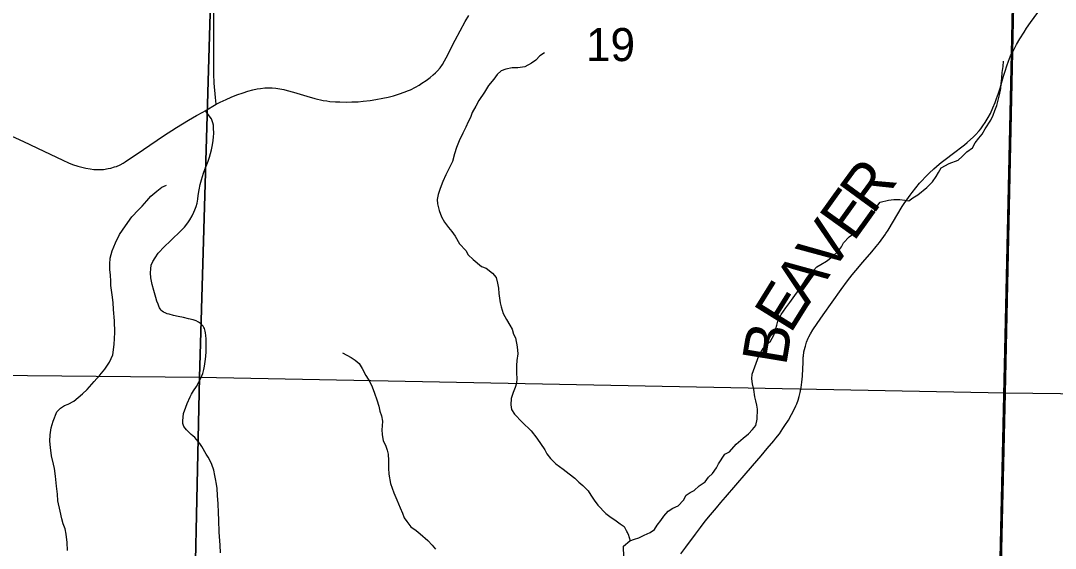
# Model space of a CAD drawing. Extents: x 0 to 34, y 0 to 22.
# Drawn here: x 5.283 to 6.594, y 14.696 to 15.364 of the extents above; entities that cross this region are included whole.
import ezdxf

# ---------------------------------------------------------------- set-up
doc = ezdxf.new("R2010")
doc.units = 0
for name, color, linetype in [('GM_X_Corporation', 7, 'Continuous'), ('GM_X_County_Road_Text', 7, 'Continuous'), ('GM_X_Interchange_Ramps', 7, 'Continuous'), ('GM_X_Interstate_Route', 7, 'Continuous'), ('GM_X_Major_Lake', 7, 'Continuous'), ('GM_X_Minor_Lake', 7, 'Continuous'), ('GM_X_Township_Road_Text', 7, 'Continuous'), ('GM_X_Unincorporated_Text', 7, 'Continuous')]:
    doc.layers.add(name, color=color, linetype=linetype)

msp = doc.modelspace()

# ---------------------------------------------------------------- linework, layer by layer
at = {"layer": 'GM_X_Corporation'}
msp.add_line((5.5168, 15.2503), (5.5307, 15.2585), dxfattribs=at)
for points in [[(6.5452, 15.3343), (6.5495, 15.3413), (6.5548, 15.3499), (6.5578, 15.3549), (6.563, 15.3623), (6.5675, 15.3683), (6.5735, 15.3765), (6.5781, 15.3825), (6.583, 15.3891), (6.5864, 15.3936), (6.5904, 15.3992), (6.594, 15.404), (6.5973, 15.4086), (6.6007, 15.4135), (6.6049, 15.4191), (6.6077, 15.4229)], [(5.5307, 15.2585), (5.5358, 15.261), (5.5433, 15.2647), (5.5499, 15.2676), (5.557, 15.2704), (5.565, 15.2731), (5.571, 15.275), (5.5775, 15.2768), (5.5828, 15.278), (5.5872, 15.2787), (5.5926, 15.2793), (5.5964, 15.2794), (5.6016, 15.2793), (5.6066, 15.2788), (5.6115, 15.2781), (5.6167, 15.2771), (5.6206, 15.2761), (5.6288, 15.2738), (5.6456, 15.2688), (5.656, 15.2658), (5.6592, 15.265), (5.6629, 15.2642), (5.6666, 15.2633), (5.6711, 15.2627), (5.6748, 15.2622), (5.6822, 15.2615), (5.6877, 15.2614), (5.6964, 15.2613), (5.7028, 15.2614), (5.7106, 15.2618), (5.7173, 15.2623), (5.7261, 15.2634), (5.7334, 15.2645), (5.7421, 15.2661), (5.749, 15.2677), (5.7556, 15.2694), (5.7631, 15.2718), (5.7692, 15.2738), (5.7744, 15.2759), (5.777, 15.277), (5.7833, 15.2802), (5.7881, 15.2829), (5.7916, 15.2851), (5.7969, 15.2886), (5.8019, 15.2924), (5.8059, 15.2956), (5.8087, 15.2982), (5.8112, 15.301), (5.8148, 15.3048), (5.8177, 15.309), (5.8204, 15.3134), (5.8225, 15.3175), (5.8339, 15.3397), (5.84, 15.3517), (5.8464, 15.3632), (5.8509, 15.3708)], [(6.3797, 15.0948), (6.3824, 15.0992), (6.4005, 15.129), (6.403, 15.1328), (6.4106, 15.1435), (6.4132, 15.1469), (6.4225, 15.1584), (6.4252, 15.1615), (6.4299, 15.1664), (6.4346, 15.1711), (6.4404, 15.1766), (6.4473, 15.1827), (6.4498, 15.1847), (6.4564, 15.1898), (6.4638, 15.1955), (6.4795, 15.2072), (6.4829, 15.2099), (6.4908, 15.2171), (6.4933, 15.2197), (6.4979, 15.2249), (6.4999, 15.2274), (6.5026, 15.2311), (6.5055, 15.2353), (6.507, 15.2376), (6.5093, 15.2416), (6.5121, 15.2469), (6.5154, 15.2538), (6.5183, 15.2607), (6.5201, 15.2657), (6.5224, 15.2725), (6.5244, 15.2791), (6.527, 15.2881), (6.5288, 15.2941), (6.5308, 15.3005), (6.533, 15.3072), (6.5351, 15.3132), (6.5364, 15.3167), (6.5378, 15.3199), (6.5404, 15.3251), (6.5431, 15.3302), (6.5452, 15.3343)], [(5.2662, 15.2207), (5.2868, 15.2112), (5.3123, 15.1992), (5.3364, 15.1876), (5.3437, 15.1843), (5.3487, 15.1824), (5.3555, 15.1802), (5.3606, 15.1787), (5.3658, 15.1776), (5.371, 15.1766), (5.3759, 15.1761), (5.3802, 15.1759), (5.388, 15.1761), (5.3941, 15.177), (5.3973, 15.1777), (5.4021, 15.1791), (5.4044, 15.1799), (5.4091, 15.182), (5.4128, 15.184), (5.4153, 15.1855), (5.4385, 15.2012), (5.4639, 15.2185), (5.4806, 15.2293), (5.4957, 15.2384), (5.5058, 15.2444), (5.5138, 15.2487), (5.5168, 15.2503)], [(6.1199, 14.689), (6.126, 14.6974), (6.1382, 14.714), (6.1447, 14.7226), (6.1508, 14.7304), (6.1575, 14.7386), (6.165, 14.7473), (6.1706, 14.7539), (6.1765, 14.7609), (6.2025, 14.7911), (6.2162, 14.8069), (6.2216, 14.8132), (6.2293, 14.8224), (6.2377, 14.8323), (6.2402, 14.8355), (6.2447, 14.8412), (6.249, 14.8476), (6.2518, 14.8517), (6.2561, 14.8584), (6.2602, 14.8655), (6.2626, 14.8701), (6.2657, 14.8767), (6.2668, 14.8792), (6.2685, 14.8837), (6.2698, 14.8882), (6.2711, 14.8936), (6.2722, 14.8996), (6.2733, 14.9067), (6.2739, 14.9143), (6.2744, 14.9239), (6.2747, 14.9309), (6.275, 14.9383), (6.2752, 14.9396), (6.2758, 14.9448), (6.2772, 14.9509), (6.2776, 14.9523), (6.2792, 14.957), (6.2813, 14.9621), (6.2821, 14.964), (6.2841, 14.9677), (6.2872, 14.9726), (6.2927, 14.9809), (6.3, 14.9916), (6.3232, 15.0239), (6.3312, 15.0349), (6.3369, 15.0425), (6.3415, 15.0481), (6.3504, 15.0585), (6.3618, 15.0715), (6.3675, 15.0783), (6.3714, 15.0835), (6.3791, 15.0939), (6.3797, 15.0948)]]:
    msp.add_lwpolyline(points, dxfattribs=at)
at = {"layer": 'GM_X_Interchange_Ramps'}
msp.add_lwpolyline([(2.1, 17.9098), (2.1, 14.1), (6.5113, 14.1), (6.5389, 15.3228), (6.5411, 15.4243), (6.5572, 16.1864), (6.5647, 16.5359), (6.5883, 17.471), (6.5943, 17.9356)], dxfattribs=at)
msp.add_lwpolyline([(6.5113, 14.1), (8.9, 14.1), (8.9, 17.8921), (8.5492, 17.9006), (8.3297, 17.9059), (7.6027, 17.9156), (6.5943, 17.9356), (6.5883, 17.471), (6.5647, 16.5359), (6.5572, 16.1864), (6.5411, 15.4243), (6.5389, 15.3228)], close=True, dxfattribs=at)
at = {"layer": 'GM_X_Interstate_Route'}
msp.add_line((5.5168, 15.2503), (5.5307, 15.2585), dxfattribs=at)
for points in [[(5.5307, 15.2585), (5.5299, 15.2669), (5.5283, 15.2851), (5.5281, 15.2886), (5.528, 15.2935), (5.5278, 15.3828)], [(5.5365, 14.6904), (5.5357, 14.6999), (5.5348, 14.7166), (5.5342, 14.7318), (5.5338, 14.7415), (5.5334, 14.7522), (5.5327, 14.7629), (5.532, 14.772), (5.5313, 14.7775), (5.5301, 14.7839), (5.5292, 14.7884), (5.5277, 14.7949), (5.5253, 14.8021), (5.5231, 14.8069), (5.5206, 14.8115), (5.5183, 14.8154), (5.5126, 14.8248), (5.5099, 14.8288), (5.5058, 14.8338), (5.5036, 14.8363), (5.5014, 14.8384), (5.499, 14.8404), (5.4964, 14.8427), (5.4931, 14.846), (5.4899, 14.8504), (5.4887, 14.854), (5.4884, 14.8576), (5.4894, 14.8667), (5.4922, 14.875), (5.494, 14.8793), (5.4977, 14.8878), (5.4995, 14.8912), (5.5021, 14.8957), (5.5057, 14.901), (5.5092, 14.9072), (5.5111, 14.9109), (5.5127, 14.9144), (5.5138, 14.9176), (5.5152, 14.9224), (5.516, 14.9268), (5.5169, 14.9325), (5.5177, 14.9391), (5.518, 14.9455), (5.5181, 14.9565), (5.518, 14.9613), (5.5177, 14.9655), (5.5172, 14.9692), (5.5169, 14.9713), (5.5165, 14.9729), (5.516, 14.9745), (5.5152, 14.9759), (5.5142, 14.9775), (5.5131, 14.9788), (5.5108, 14.9809), (5.5083, 14.9825), (5.5054, 14.984), (5.5017, 14.9853), (5.4958, 14.9869), (5.4895, 14.9883), (5.4828, 14.9897), (5.4767, 14.9911), (5.4713, 14.9925), (5.4685, 14.9932), (5.466, 14.9942), (5.464, 14.9953), (5.4625, 14.9966), (5.4612, 14.9977), (5.46, 14.9994), (5.4591, 15.0008), (5.4582, 15.0027), (5.4573, 15.0051), (5.4558, 15.0093), (5.4544, 15.0137), (5.4517, 15.0226), (5.4498, 15.0302), (5.4482, 15.0385), (5.4475, 15.0448), (5.4478, 15.0502), (5.4486, 15.0545), (5.4505, 15.0592), (5.4535, 15.0642), (5.4575, 15.0699), (5.4652, 15.0783), (5.4727, 15.0853), (5.4873, 15.0994), (5.4905, 15.1029), (5.4949, 15.1084), (5.4974, 15.1123), (5.5002, 15.117), (5.5027, 15.122), (5.5039, 15.1248), (5.5055, 15.129), (5.5067, 15.1331), (5.5077, 15.1384), (5.5082, 15.143), (5.5093, 15.1503), (5.5106, 15.1569), (5.5121, 15.1628), (5.5133, 15.167), (5.5147, 15.1714), (5.5166, 15.176), (5.5205, 15.1864), (5.5223, 15.1914), (5.5238, 15.196), (5.5251, 15.2009), (5.5263, 15.2071), (5.527, 15.2125), (5.5275, 15.2172), (5.5277, 15.2217), (5.5276, 15.2286), (5.5273, 15.232), (5.5267, 15.235), (5.5259, 15.2376), (5.5248, 15.24), (5.5233, 15.2423), (5.5198, 15.2467), (5.518, 15.2489), (5.5168, 15.2503)]]:
    msp.add_lwpolyline(points, dxfattribs=at)
at = {"layer": 'GM_X_Minor_Lake'}
for points in [[(5.5393, 15.9226), (5.5097, 14.9125), (4.5059, 14.9222), (4.5275, 15.9394)], [(6.553, 15.9139), (6.5307, 14.8925), (5.5097, 14.9125), (5.5393, 15.9226)], [(7.5725, 15.8874), (7.5466, 14.8803), (6.5307, 14.8925), (6.553, 15.9139)]]:
    msp.add_lwpolyline(points, close=True, dxfattribs=at)
at = {"layer": 'GM_X_Township_Road_Text'}
for points in [[(5.9468, 15.3235), (5.9412, 15.32), (5.936, 15.3146), (5.9307, 15.3107), (5.9221, 15.306), (5.913, 15.3048), (5.9062, 15.3047), (5.8979, 15.303), (5.8919, 15.301), (5.887, 15.2964), (5.8826, 15.2902), (5.8759, 15.2821), (5.8711, 15.2737), (5.8637, 15.2633), (5.86, 15.256), (5.8552, 15.2479), (5.853, 15.2418), (5.8501, 15.2364), (5.8471, 15.2296), (5.8435, 15.2219), (5.839, 15.2123), (5.8354, 15.2039), (5.8329, 15.1958), (5.8303, 15.1859), (5.8252, 15.1759), (5.8219, 15.169), (5.8182, 15.1606), (5.8146, 15.1518), (5.812, 15.1441), (5.811, 15.138), (5.8114, 15.1323), (5.8135, 15.124), (5.8166, 15.116), (5.8201, 15.1092), (5.8255, 15.1025), (5.8297, 15.0972), (5.8336, 15.0916), (5.8394, 15.0818), (5.8471, 15.0731), (5.8502, 15.0678), (5.8564, 15.0618), (5.8671, 15.0532), (5.8732, 15.051), (5.8809, 15.0447), (5.8859, 15.0391), (5.8875, 15.0318), (5.8887, 15.0254), (5.8892, 15.0189), (5.8909, 15.0068), (5.8921, 15.0018), (5.8945, 14.9935), (5.8988, 14.986), (5.903, 14.9788), (5.9058, 14.9735), (5.9077, 14.9674), (5.9101, 14.9625), (5.9125, 14.9512), (5.913, 14.9424), (5.912, 14.934), (5.9113, 14.9275), (5.9115, 14.918), (5.912, 14.9112), (5.9117, 14.9051), (5.9099, 14.8997), (5.9073, 14.8932), (5.9048, 14.886), (5.9041, 14.8776), (5.905, 14.8719), (5.9088, 14.8658), (5.9188, 14.8557), (5.93, 14.8448), (5.9373, 14.8354), (5.9474, 14.8207), (5.9501, 14.8158), (5.9547, 14.8098), (5.9612, 14.8031), (5.9708, 14.7964), (5.9781, 14.7904), (5.9854, 14.7848), (5.9904, 14.7799), (5.9957, 14.7758), (6.0023, 14.7687), (6.0057, 14.7634), (6.01, 14.757), (6.0146, 14.7506), (6.0246, 14.7401), (6.0296, 14.7364), (6.038, 14.7308), (6.043, 14.727), (6.048, 14.7237), (6.0507, 14.7188), (6.053, 14.7139), (6.0556, 14.7057)], [(6.2135, 14.926), (6.2186, 14.9398), (6.223, 14.9475), (6.2279, 14.954), (6.2335, 14.9583), (6.2375, 14.966), (6.2415, 14.9786), (6.2429, 14.9839), (6.247, 14.9924), (6.2529, 15.0005), (6.2581, 15.0074), (6.2641, 15.0162), (6.27, 15.0243), (6.2748, 15.0309), (6.2785, 15.037), (6.2826, 15.0424), (6.2878, 15.0478), (6.2923, 15.0528), (6.2972, 15.0556), (6.3043, 15.0599), (6.3118, 15.0653), (6.3196, 15.073), (6.3234, 15.078), (6.3259, 15.083), (6.333, 15.0904), (6.3386, 15.0946), (6.3435, 15.0985), (6.3499, 15.1032), (6.3558, 15.1105), (6.3618, 15.1167), (6.3647, 15.1224), (6.3684, 15.129), (6.3725, 15.1344), (6.3831, 15.1372), (6.3899, 15.1377), (6.3974, 15.1378), (6.4039, 15.1371), (6.4088, 15.1361), (6.4137, 15.1399), (6.4201, 15.1438), (6.4317, 15.1532), (6.4388, 15.1601), (6.4436, 15.167), (6.4462, 15.172), (6.4499, 15.1782), (6.46, 15.1833), (6.4713, 15.1876), (6.4765, 15.1923), (6.4825, 15.1981), (6.4893, 15.2035), (6.4929, 15.2097), (6.4974, 15.2154), (6.5019, 15.2208), (6.5056, 15.2274), (6.5126, 15.2385), (6.5155, 15.2446), (6.5177, 15.2508), (6.5203, 15.2569), (6.5235, 15.2706), (6.5253, 15.2787), (6.5259, 15.2848), (6.5266, 15.2916), (6.5272, 15.2989), (6.5283, 15.3065), (6.5289, 15.313)], [(5.4021, 14.9843), (5.4007, 14.9987), (5.4002, 15.0075), (5.3989, 15.0173), (5.3973, 15.0291), (5.3972, 15.0344), (5.3967, 15.042), (5.3962, 15.0493), (5.3961, 15.0561), (5.3964, 15.0634), (5.3989, 15.0729), (5.4033, 15.0832), (5.4084, 15.0936), (5.4158, 15.1047), (5.424, 15.1159), (5.4322, 15.1248), (5.4371, 15.1294), (5.443, 15.1364), (5.4478, 15.1421), (5.4557, 15.1483), (5.4621, 15.1534), (5.4677, 15.1561)], [(5.3423, 14.6934), (5.3418, 14.7036), (5.3405, 14.7139), (5.3393, 14.7207), (5.3369, 14.7271), (5.3353, 14.7332), (5.3329, 14.7431), (5.3301, 14.756), (5.3296, 14.7647), (5.3286, 14.7746), (5.3273, 14.7875), (5.3257, 14.797), (5.3245, 14.8027), (5.322, 14.8133), (5.3207, 14.8236), (5.3199, 14.8319), (5.3205, 14.8396), (5.3215, 14.8487), (5.324, 14.8571), (5.3288, 14.869), (5.3336, 14.8736), (5.3385, 14.8768), (5.3434, 14.8787), (5.3502, 14.8826), (5.3614, 14.8916), (5.3674, 14.897), (5.3763, 14.9074), (5.3834, 14.9155), (5.3897, 14.9228), (5.3956, 14.932), (5.3997, 14.9412), (5.4017, 14.9542), (5.4023, 14.9694), (5.4021, 14.9843)], [(5.6908, 14.9436), (5.7018, 14.9377), (5.7072, 14.9344), (5.7122, 14.9303), (5.716, 14.9238), (5.7207, 14.9148), (5.7258, 14.9069), (5.7285, 14.9004), (5.7316, 14.8925), (5.7344, 14.8842), (5.7368, 14.8762), (5.7384, 14.8697), (5.7404, 14.8637), (5.7416, 14.8569), (5.7413, 14.8511), (5.741, 14.8462), (5.7411, 14.8401), (5.7424, 14.8321), (5.7455, 14.8268), (5.7475, 14.8204), (5.7487, 14.8151), (5.7492, 14.8071), (5.7493, 14.7976), (5.7498, 14.79), (5.7519, 14.7782), (5.7558, 14.7665), (5.7597, 14.7574), (5.7641, 14.7472), (5.7668, 14.7404), (5.7692, 14.7347), (5.7726, 14.7298), (5.7777, 14.7234), (5.7845, 14.7186), (5.7895, 14.7145), (5.7991, 14.7059), (5.8045, 14.7002), (5.8087, 14.695)], [(6.0474, 14.6849), (6.0472, 14.6989), (6.0551, 14.7055), (6.0611, 14.7075), (6.0664, 14.7095), (6.0735, 14.7127), (6.081, 14.7162), (6.0863, 14.7197), (6.09, 14.7255), (6.0944, 14.7312), (6.0981, 14.7366), (6.1037, 14.7432), (6.1097, 14.7471), (6.1165, 14.7498), (6.1232, 14.7572), (6.1265, 14.7633), (6.1318, 14.7668), (6.1367, 14.7692), (6.143, 14.775), (6.1505, 14.7801), (6.155, 14.7862), (6.1598, 14.7909), (6.165, 14.7978), (6.1676, 14.8032), (6.1757, 14.8151), (6.1814, 14.8182), (6.1899, 14.8278), (6.1989, 14.8356), (6.2057, 14.841), (6.2105, 14.8464), (6.215, 14.8514), (6.2167, 14.8598), (6.2169, 14.8724), (6.2161, 14.8773), (6.2149, 14.883), (6.2137, 14.888), (6.2124, 14.8971), (6.2108, 14.9043), (6.2099, 14.9107), (6.2102, 14.9168), (6.2135, 14.926)], [(6.0512, 14.7163), (6.0511, 14.7165)]]:
    msp.add_lwpolyline(points, dxfattribs=at)
at = {"layer": 'GM_X_Unincorporated_Text'}
for points in [[(4.484, 14.1), (5.492, 14.1), (5.5097, 14.9125), (4.5059, 14.9222)], [(5.492, 14.1), (6.5122, 14.1), (6.5307, 14.8925), (5.5097, 14.9125)], [(6.5122, 14.1), (7.5285, 14.1), (7.5466, 14.8803), (6.5307, 14.8925)]]:
    msp.add_lwpolyline(points, close=True, dxfattribs=at)

# ---------------------------------------------------------------- texts
at = {"layer": 'GM_X_County_Road_Text'}
msp.add_text('19', height=0.04186, rotation=0, dxfattribs=at).set_placement((5.9995, 15.3132))
at = {"layer": 'GM_X_Major_Lake'}
for s, rotation, p in [('R', 53.8108, (6.3635, 15.1176)), ('E', 54.3353, (6.3388, 15.0832)), ('V', 54.3374, (6.3097, 15.0426)), ('A', 54.395, (6.2806, 15.002)), ('E', 58.1182, (6.2587, 14.9667)), ('B', 80.6814, (6.2532, 14.9261))]:
    msp.add_text(s, height=0.0568, rotation=rotation, dxfattribs=at).set_placement(p)

doc.saveas('drawing.dxf')
